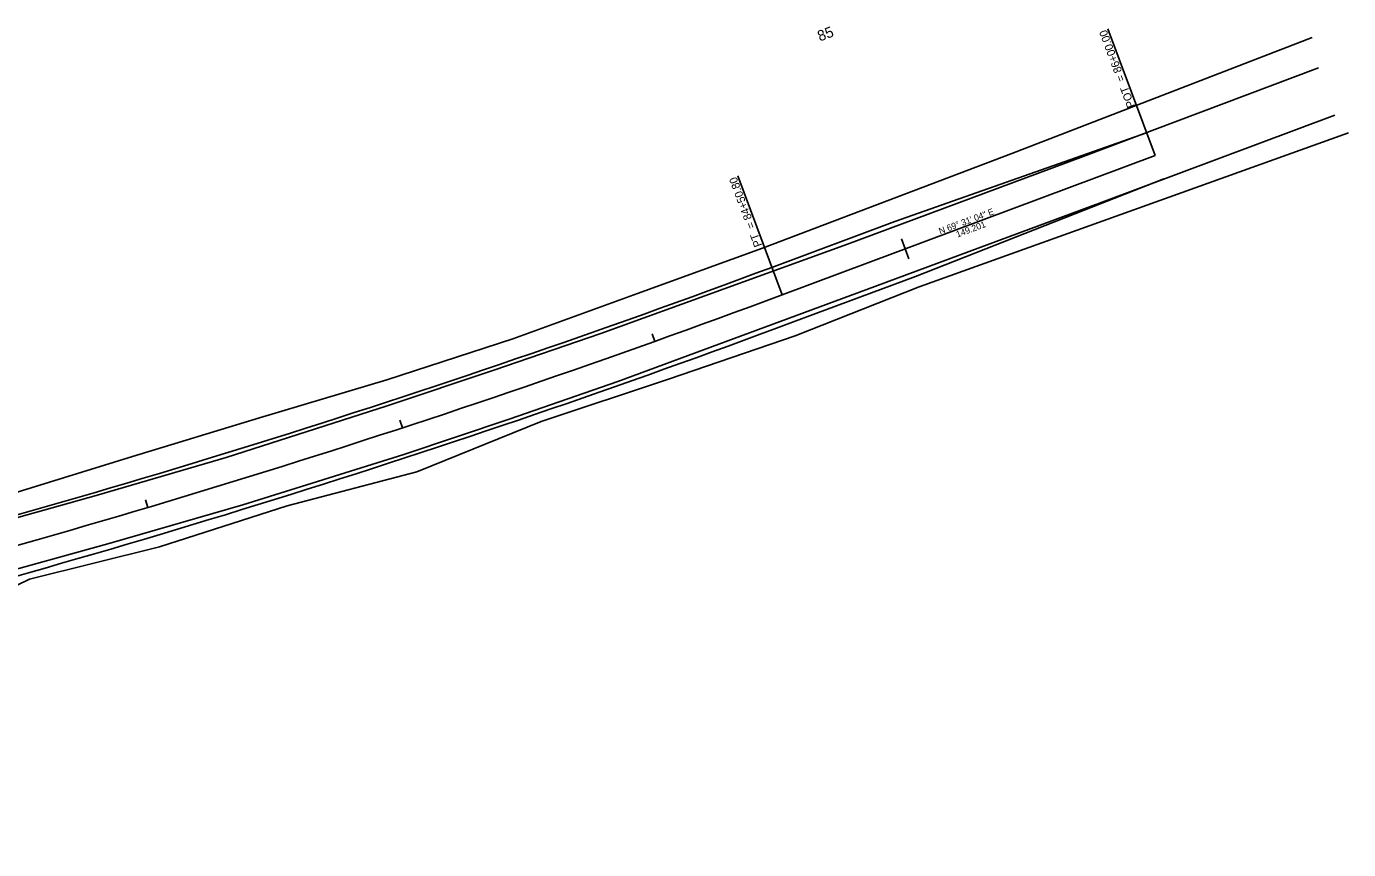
# Model space of a CAD drawing. Extents: x 1965724 to 1970316, y 1117080 to 1118173.
# Drawn here: x 1969820.9 to 1970316.3, y 1117864.9 to 1118173.5 of the extents above; entities that cross this region are included whole.
import ezdxf

# ---------------------------------------------------------------- set-up
doc = ezdxf.new("R2010")
doc.units = 0
for name, color, linetype in [('RD_EX_Road', 7, 'Continuous'), ('RD_EX_RW', 7, 'Continuous'), ('RD_HC_CL', 7, 'Continuous'), ('RD_HC_Data', 7, 'Continuous'), ('RD_HC_TX_Sta20', 7, 'Continuous'), ('RD_PD_Final_TrvlWay', 7, 'Continuous')]:
    doc.layers.add(name, color=color, linetype=linetype)

msp = doc.modelspace()

# ---------------------------------------------------------------- linework, layer by layer
at = {"layer": 'RD_EX_Road'}
for points in [[(1969956.01, 1118031.22), (1969995.96, 1118044.64), (1970036.15, 1118058.36), (1970128.54, 1118091.88), (1970215.92, 1118124.32), (1970305.09, 1118157.99)], [(1969962.32, 1118012.96), (1970001.79, 1118026.28), (1970042.53, 1118040.39), (1970135.38, 1118074.72), (1970223.98, 1118107.67), (1970311.23, 1118140.24)], [(1969810.79, 1117987.5), (1969847.01, 1117997.58), (1969895.73, 1118011.88), (1969956.01, 1118031.22)], [(1969282.94, 1117875.42), (1969323.91, 1117876.08), (1969374.87, 1117877.05), (1969422.79, 1117880.61), (1969473.42, 1117886.58), (1969522.56, 1117895.49), (1969570.22, 1117905.24), (1969616.1, 1117916.13), (1969665.76, 1117928.56), (1969710.86, 1117940.59), (1969757.15, 1117953.18), (1969805.29, 1117966.74), (1969852.3, 1117979.83), (1969901.94, 1117994.12), (1969962.32, 1118012.96)]]:
    msp.add_lwpolyline(points, dxfattribs=at)
at = {"layer": 'RD_EX_RW'}
for points in [[(1969572.11, 1117933.1), (1969620.65, 1117945.09), (1969669.27, 1117956.79), (1969717.46, 1117970), (1969765.52, 1117982.9), (1969860.61, 1118012.25), (1969908.19, 1118026.72), (1969955.86, 1118040.95), (1970003.14, 1118056.43), (1970049.91, 1118073.39), (1970096.65, 1118090.41), (1970143.42, 1118108.08), (1970190.16, 1118125.84), (1970302.63, 1118169.37)], [(1969278.26, 1117865.85), (1969329.18, 1117864.9), (1969380.05, 1117867.15), (1969430.95, 1117869.7), (1969481.52, 1117876.2), (1969532.27, 1117882.45), (1969582.19, 1117893.11), (1969628.5, 1117913.96), (1969678.44, 1117920.38), (1969727.34, 1117931.16), (1969776, 1117943.94), (1969821.95, 1117966.31), (1969870.71, 1117978.39), (1969918.52, 1117993.72), (1969967.17, 1118006.46), (1970013.77, 1118025.42), (1970061.42, 1118041.22), (1970108.95, 1118057.46), (1970155.44, 1118075.9), (1970316.32, 1118133.6)]]:
    msp.add_lwpolyline(points, dxfattribs=at)
at = {"layer": 'RD_HC_CL'}
msp.add_line((1970104.05, 1118072.87), (1970243.81, 1118125.08), dxfattribs=at)
msp.add_arc((1968809.03, 1121539.8), 3700.9, 284.14929, 290.48234, dxfattribs=at)
at = {"layer": 'RD_HC_Data'}
for p, q in [((1970243.81, 1118125.08), (1970226.06, 1118172.62)), ((1970104.05, 1118072.87), (1970087.4, 1118117.43)), ((1970150.14, 1118090.09), (1970148.74, 1118093.84)), ((1970150.14, 1118090.09), (1970151.54, 1118086.34)), ((1970056.34, 1118055.42), (1970055.33, 1118058.25)), ((1969961.74, 1118023), (1969960.81, 1118025.85)), ((1969866.31, 1117993.14), (1969865.45, 1117996.01))]:
    msp.add_line(p, q, dxfattribs=at)
at = {"layer": 'RD_PD_Final_TrvlWay'}
for p, q in [((1970146.29, 1118100.39), (1970240.62, 1118133.65)), ((1970153.99, 1118079.78), (1970247.09, 1118116.3)), ((1970100.2, 1118083.18), (1970146.29, 1118100.39)), ((1970107.89, 1118062.57), (1970153.99, 1118079.78)), ((1970153.99, 1118079.78), (1970153.99, 1118079.78))]:
    msp.add_line(p, q, dxfattribs=at)
for radius in [3689.9, 3711.9]:
    msp.add_arc((1968809.03, 1121539.8), radius, 284.14929, 290.48234, dxfattribs=at)

# ---------------------------------------------------------------- texts
at = {"layer": 'RD_HC_Data'}
for s, height, rotation, p in [('POT  = 86+00.00', 3, 110.4823, (1970236.35, 1118143.64)), ('PT  = 84+50.80', 3, 110.4823, (1970096.58, 1118091.43)), ('N 69%%d 31\' 04" E', 2.4, 20.4823, (1970163.3, 1118095.54)), ('149.201', 2.4, 20.4823, (1970169.75, 1118094.32))]:
    msp.add_text(s, height=height, rotation=rotation, dxfattribs=at).set_placement(p)
at = {"layer": 'RD_HC_TX_Sta20'}
msp.add_text('85', height=4, rotation=20.4823, dxfattribs=at).set_placement((1970118.18, 1118167.82))

doc.saveas('drawing.dxf')
